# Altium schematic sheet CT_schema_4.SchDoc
size 479 x 328 mm
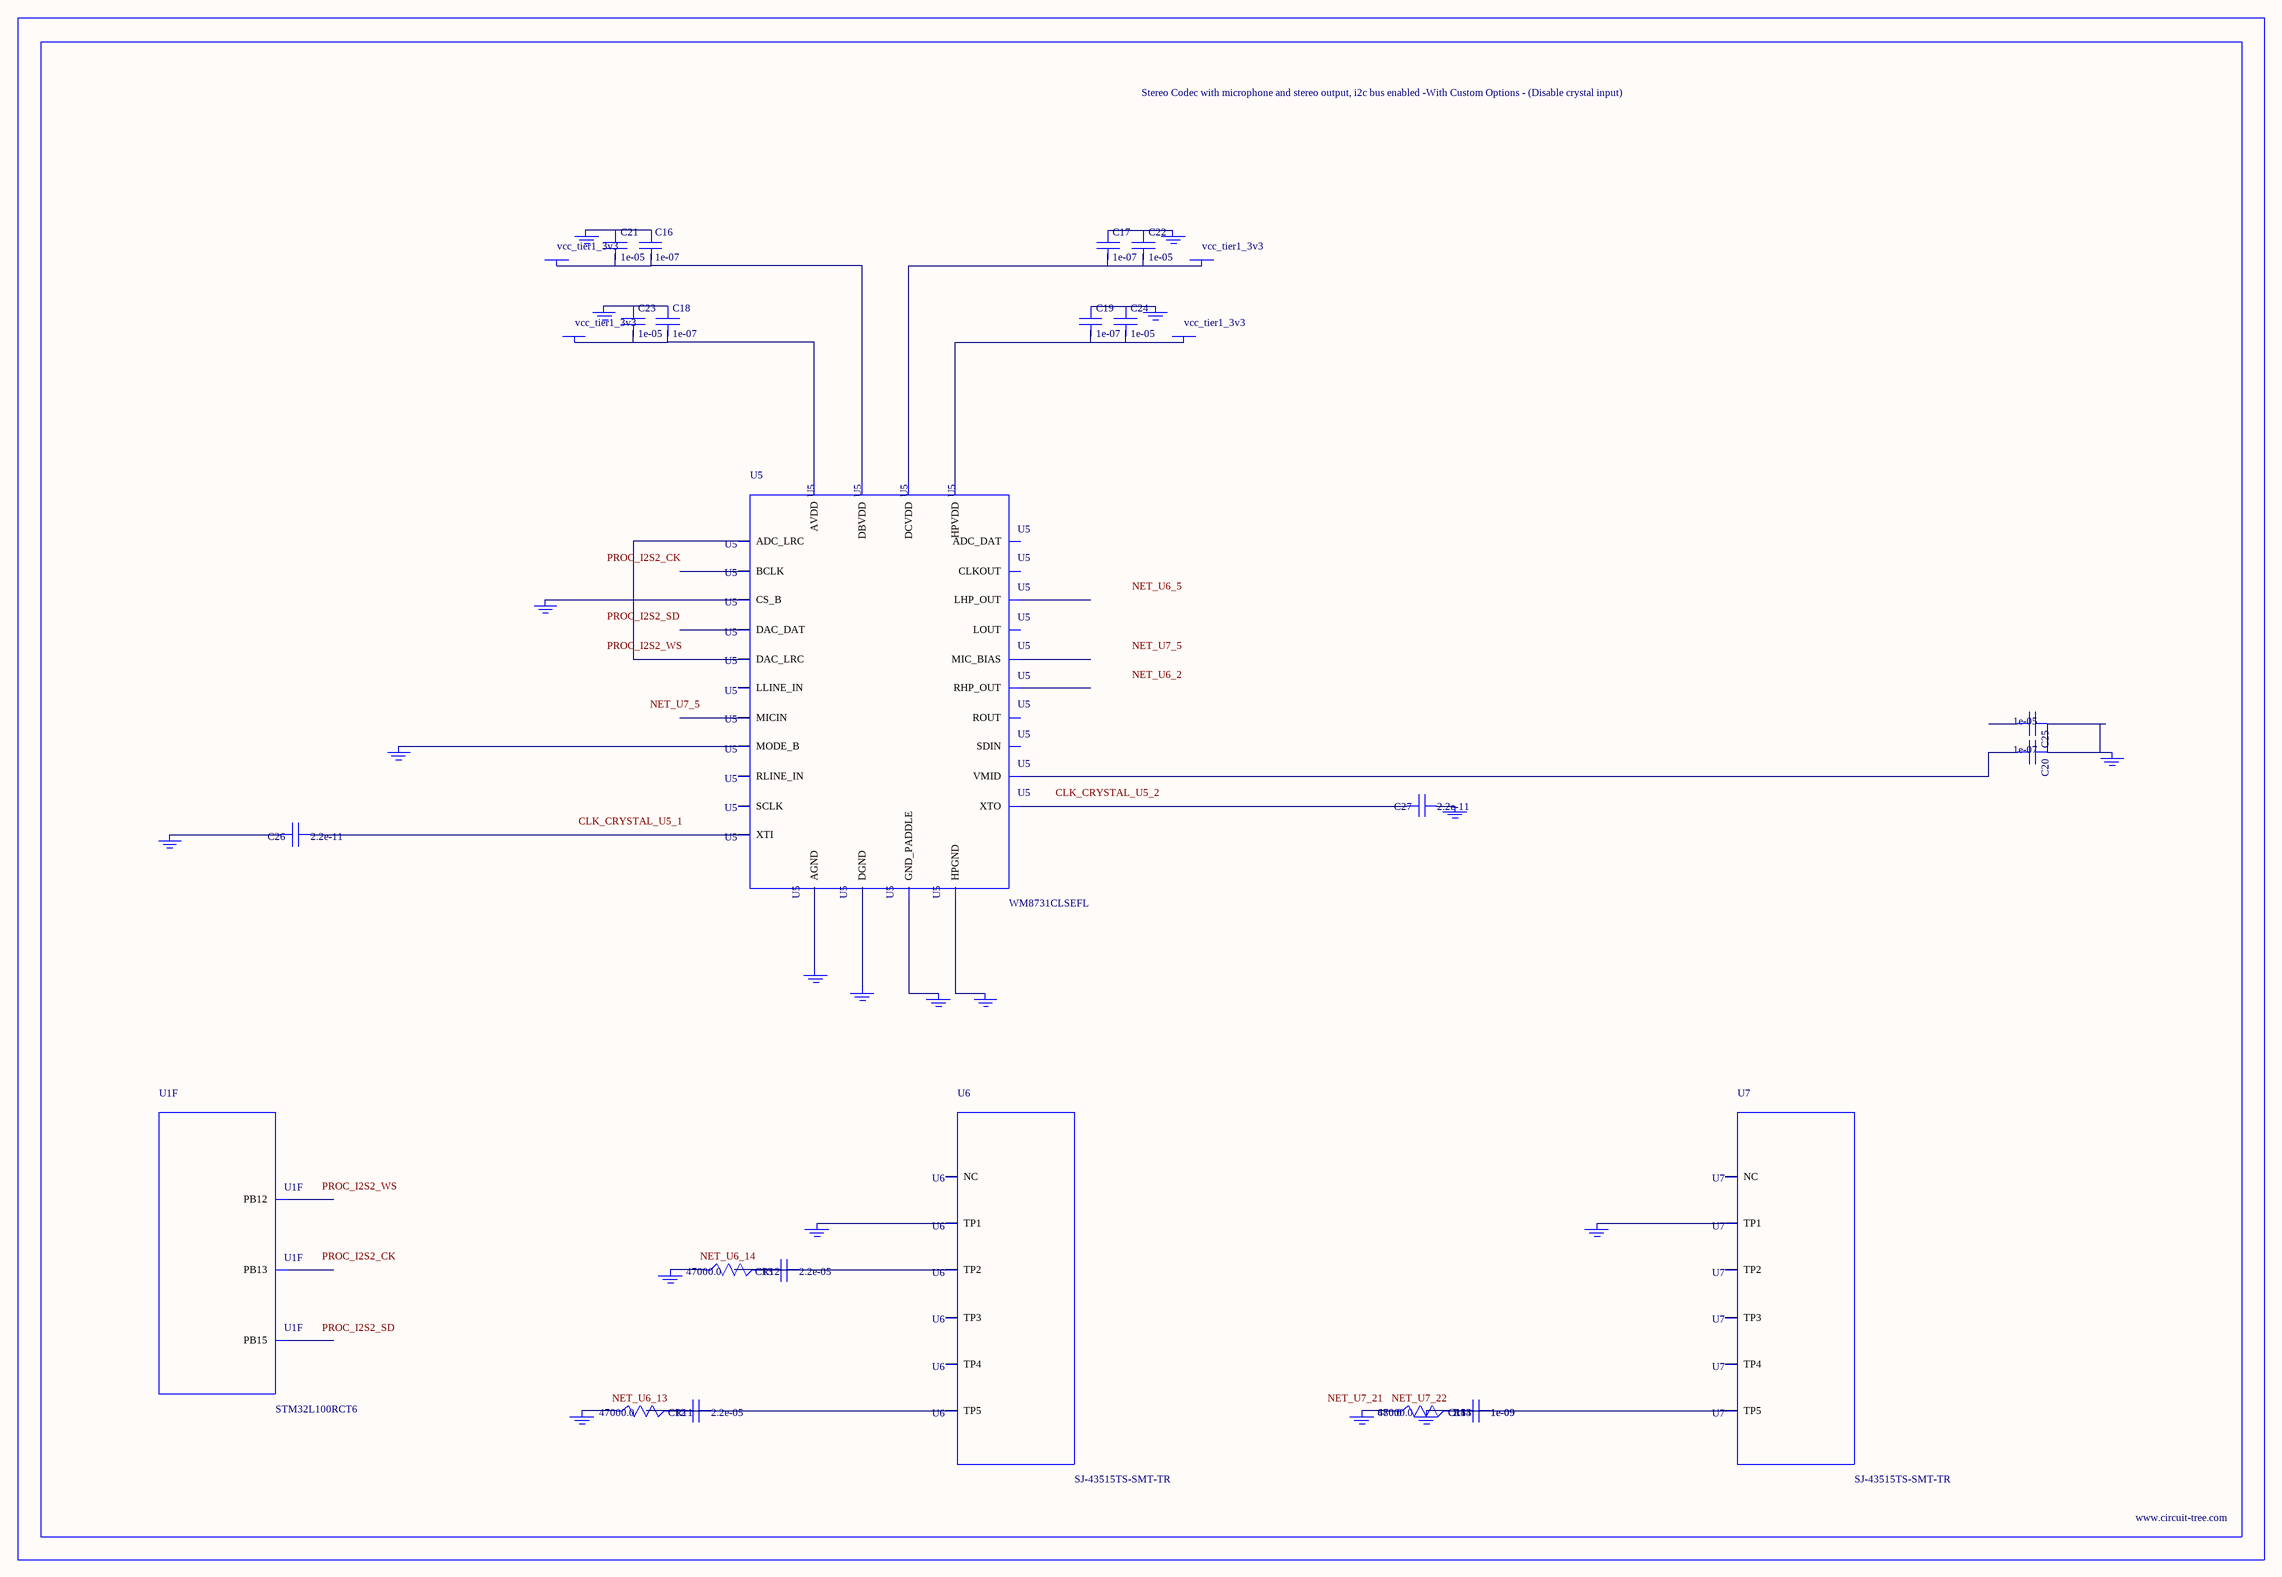
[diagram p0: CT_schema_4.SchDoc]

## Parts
BORDER3  (no value)
C12  2.2e-05  [C1210]
C13  2.2e-05  [C1210]
C14  1e-09  [C0402]
C15  1e-09  [C0402]
C16  1e-07  [C0402]
C17  1e-07  [C0402]
C18  1e-07  [C0402]
C19  1e-07  [C0402]
C20  1e-07  [C0402]
C21  1e-05  [C0805]
C22  1e-05  [C0805]
C23  1e-05  [C0805]
C24  1e-05  [C0805]
C25  1e-05  [C0805]
C26  2.2e-11  [C0402]
C27  2.2e-11  [C0402]
GND_INSTANCE_3_0  (no value)
GND_INSTANCE_3_1  (no value)
GND_INSTANCE_3_2  (no value)
GND_INSTANCE_3_3  (no value)
GND_INSTANCE_3_4  (no value)
GND_INSTANCE_3_5  (no value)
GND_INSTANCE_3_6  (no value)
GND_INSTANCE_3_7  (no value)
GND_INSTANCE_3_8  (no value)
GND_INSTANCE_3_9  (no value)
GND_INSTANCE_3_10  (no value)
GND_INSTANCE_3_11  (no value)
GND_INSTANCE_3_12  (no value)
GND_INSTANCE_3_13  (no value)
GND_INSTANCE_3_14  (no value)
GND_INSTANCE_3_15  (no value)
GND_INSTANCE_3_16  (no value)
GND_INSTANCE_3_17  (no value)
GND_INSTANCE_3_18  (no value)
POWER_INSTANCE_3_0  vcc_tier1_3v3
POWER_INSTANCE_3_1  vcc_tier1_3v3
POWER_INSTANCE_3_2  vcc_tier1_3v3
POWER_INSTANCE_3_3  vcc_tier1_3v3
R11  47000.0  [R0603]
R12  47000.0  [R0603]
R13  47000.0  [R0603]
R14  680.0  [R0603]
U1  STM32L100RCT6  [LQFP64]  (part F of 7)
U5  WM8731CLSEFL  [QFN-28]
U6  SJ-43515TS-SMT-TR  [SJ-43515TS-SMT-TR]
U7  SJ-43515TS-SMT-TR  [SJ-43515TS-SMT-TR]

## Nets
NetC12_1: C12.1 C12.2 R11.2 U6.5(TP5)
NetC13_1: C13.1 C13.2 R12.2 U6.2(TP2)
NetC14_1: C14.1 C14.2 C15.1 C15.2 GND_INSTANCE_3_18.0(GND) R13.2 R14.2 U7.5(TP5)
NetC16_1: C16.1 C21.1 GND_INSTANCE_3_3.0(GND)
NetC16_2: C16.2 C21.2 POWER_INSTANCE_3_1.0(PWR) U5.5(DBVDD)
NetC17_1: C17.1 C22.1 GND_INSTANCE_3_2.0(GND)
NetC17_2: C17.2 C22.2 POWER_INSTANCE_3_0.0(PWR) U5.3(DCVDD)
NetC18_1: C18.1 C23.1 GND_INSTANCE_3_6.0(GND)
NetC18_2: C18.2 C23.2 POWER_INSTANCE_3_3.0(PWR) U5.18(AVDD)
NetC19_1: C19.1 C24.1 GND_INSTANCE_3_4.0(GND)
NetC19_2: C19.2 C24.2 POWER_INSTANCE_3_2.0(PWR) U5.12(HPVDD)
NetC20_1: C20.1 C25.1 GND_INSTANCE_3_7.0(GND)
NetC20_2: C20.2 U5.20(VMID)
NetC26_1: C26.1 U5.1(XTI)
NetC26_2: C26.2 GND_INSTANCE_3_0.0(GND)
NetC27_1: C27.1 GND_INSTANCE_3_1.0(GND)
NetC27_2: C27.2 U5.2(XTO)
NetGND_INSTANCE_3_5_0: GND_INSTANCE_3_5.0(GND) U5.15(HPGND)
NetGND_INSTANCE_3_8_0: GND_INSTANCE_3_8.0(GND) U5.25(MODE_B)
NetGND_INSTANCE_3_9_0: GND_INSTANCE_3_9.0(GND) U5.26(CS_B)
NetGND_INSTANCE_3_10_0: GND_INSTANCE_3_10.0(GND) U5.29(GND_PADDLE)
NetGND_INSTANCE_3_11_0: GND_INSTANCE_3_11.0(GND) U5.4(DGND)
NetGND_INSTANCE_3_12_0: GND_INSTANCE_3_12.0(GND) U5.19(AGND)
NetGND_INSTANCE_3_13_0: GND_INSTANCE_3_13.0(GND) U6.1(TP1)
NetGND_INSTANCE_3_14_0: GND_INSTANCE_3_14.0(GND) R12.1
NetGND_INSTANCE_3_15_0: GND_INSTANCE_3_15.0(GND) R11.1
NetGND_INSTANCE_3_16_0: GND_INSTANCE_3_16.0(GND) U7.1(TP1)
NetGND_INSTANCE_3_17_0: GND_INSTANCE_3_17.0(GND) R13.1 R14.1
NetU5_9: U5.9(DAC_LRC) U5.11(ADC_LRC)

Not connected (* = marked no-connect by the designer): C25 2; U1 33(PB12) 34(PB13) 36(PB15); U5 6(CLKOUT) 7(BCLK) 8(DAC_DAT) 10(ADC_DAT) 13(LHP_OUT) 14(RHP_OUT) 16(LOUT) 17(ROUT) 21(MIC_BIAS) 22(MICIN) 23(RLINE_IN) 24(LLINE_IN) 27(SDIN) 28(SCLK); U6 3(TP3) 4(TP4) 6(NC); U7 2(TP2) 3(TP3) 4(TP4) 6(NC)

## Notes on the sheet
- Labels drawn without touching a wire or pin: CLK_CRYSTAL_U5_1, CLK_CRYSTAL_U5_2, NET_U6_2, NET_U6_5, NET_U6_13, NET_U6_14, NET_U7_5, NET_U7_21, NET_U7_22, PROC_I2S2_CK, PROC_I2S2_SD, PROC_I2S2_WS

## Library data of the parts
BORDER3 = BORDER_PAGE3
C12 C13 = C1210C224K5RACTU
C14 C15 = C0402C102K3RAC
C16-C20 = C0402C104K3RACTU
C21-C25 = C0805C106K8RACTU
C26 C27 = C0402C220K3RAC
GND_INSTANCE_3_0-GND_INSTANCE_3_18 = GND
POWER_INSTANCE_3_0-POWER_INSTANCE_3_3 = PWR
R11-R13 = RC0603JR-0747KL
R14 = RC0603JR-07680RL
